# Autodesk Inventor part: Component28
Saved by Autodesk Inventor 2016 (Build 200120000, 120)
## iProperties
Created: 2016-09
Part Number: Component28
Material: Generic
Document SubType Name: Modeling
Designer: Administrator
Appearance: Generic
Author: Administrator
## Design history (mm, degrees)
feature "Body1"
body "Solid1"
